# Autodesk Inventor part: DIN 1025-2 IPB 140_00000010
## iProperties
Created: 2006-02
Part Number: DIN 1025-2 IPB 140_00000010
Material: Default
Document SubType Name: Modeling
Designer: 40664
Manufacturer: Standard
Standards Organization: Custom
Stock Number: DIN 1025-2 IPB 140
Mass: 11082.7 g
Surface Area: 20865.2 cm^2
Volume: 11082.7 cm^3
Density: 1 g/cm^3
G_L: 2580.000 mm
G_W: 140.000 mm
G_H: 140.000 mm
AFG_Item: IPB 140
CSToolsMass: 11.0
CSToolsVolume: 11082691.0
CSToolsArea: 20865.0
Author: 40664
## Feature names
1. AFG_Detailed_DIN 1025-2 IPB 140_00000010 [Extrusion]
2. AFG_Simplified_DIN 1025-2 IPB 140_00000010 [Extrusion]
